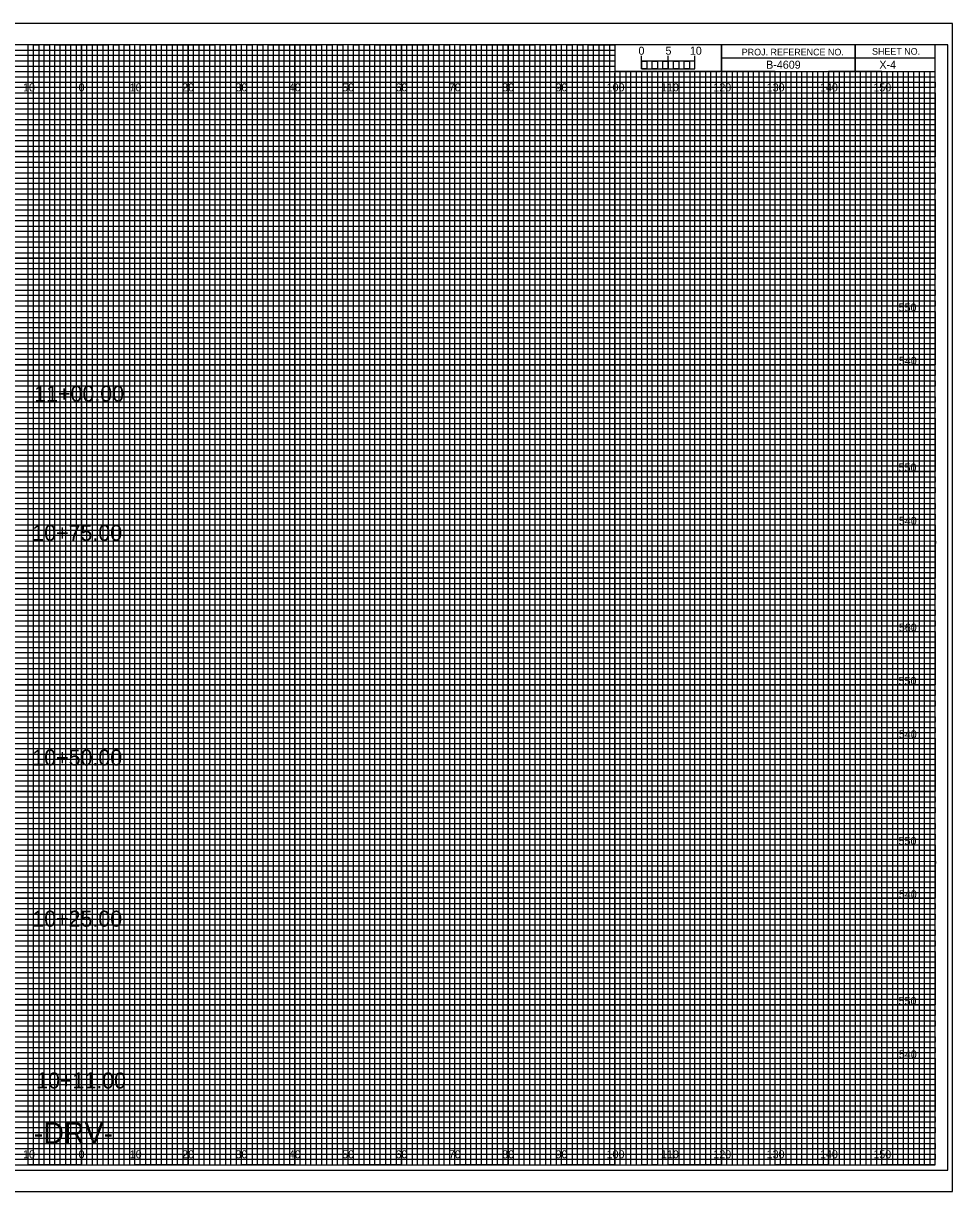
# Model space of a CAD drawing. Extents: x -13 to 323, y -5 to 214.
# Drawn here: x 149.1 to 323.3, y -5 to 214 of the extents above; entities that cross this region are included whole.
import ezdxf

# ---------------------------------------------------------------- set-up
doc = ezdxf.new("R2010")
doc.units = 0
for name, color, linetype in [('Prop XS Alignment Label', 7, 'Continuous'), ('Prop XS Bar Scale Labels', 7, 'Continuous'), ('Prop XS Elevation Labels', 7, 'Continuous'), ('Prop XS Offset Labels', 7, 'Continuous'), ('Prop XS Project Number', 7, 'Continuous'), ('Prop XS Sheet Number', 7, 'Continuous'), ('Prop XS Station Labels', 7, 'Continuous'), ('Sheet Cross Section CELL', 7, 'Continuous'), ('Sheet Cross Section Grid Major CELL', 7, 'Continuous'), ('Sheet Cross Section Grid Middle CELL', 7, 'Continuous'), ('Sheet Cross Section Grid Minor 1 CELL', 7, 'Continuous'), ('Sheet Cross Section Grid Minor 2 CELL', 7, 'Continuous'), ('Sheet Cross Section Scale CELL', 7, 'Continuous'), ('Sheet Cutting Line CELL', 7, 'Continuous'), ('Sheet DOT Grid CELL', 7, 'Continuous'), ('Sheet Plot Border Inside CELL', 7, 'Continuous'), ('Sheet Plot Border Outside CELL', 7, 'Continuous')]:
    doc.layers.add(name, color=color, linetype=linetype)

msp = doc.modelspace()

# ---------------------------------------------------------------- linework, layer by layer
at = {"layer": 'Sheet Cross Section CELL'}
for p, q in [((305, 210), (305, 205)), ((305, 205), (305, 210)), ((280, 207.5), (280, 205)), ((320, 207.49), (280, 207.49)), ((280, 205), (320, 205))]:
    msp.add_line(p, q, dxfattribs=at)
for points in [[(320, 210), (0, 210), (0, 0), (320, 0)], [(280, 210), (260, 210), (260, 205.03), (280, 205.03)], [(320, 210), (280, 210), (280, 205), (320, 205)]]:
    msp.add_lwpolyline(points, close=True, dxfattribs=at)
at = {"layer": 'Sheet Cross Section Grid Major CELL'}
for p, q in [((150, 210), (140, 210)), ((150, 0), (150, 210)), ((170, 210), (160, 210)), ((160, 210), (160, 0)), ((170, 0), (170, 210)), ((190, 210), (180, 210)), ((180, 210), (180, 0)), ((190, 0), (190, 210)), ((210, 210), (200, 210)), ((200, 210), (200, 0)), ((210, 0), (210, 210)), ((230, 210), (220, 210)), ((220, 210), (220, 0)), ((230, 0), (230, 210)), ((250, 210), (240, 210)), ((240, 210), (240, 0)), ((250, 0), (250, 210)), ((260, 210), (260, 0)), ((270, 0), (270, 205)), ((290, 205), (280, 205)), ((280, 205), (280, 0)), ((290, 0), (290, 205)), ((310, 205), (300, 205)), ((300, 205), (300, 0)), ((310, 0), (310, 205)), ((160, 0), (150, 0)), ((180, 0), (170, 0)), ((200, 0), (190, 0)), ((220, 0), (210, 0)), ((240, 0), (230, 0)), ((260, 0), (250, 0)), ((280, 0), (270, 0)), ((300, 0), (290, 0)), ((320, 0), (310, 0)), ((320, 0), (320, 0))]:
    msp.add_line(p, q, dxfattribs=at)
for points in [[(0, 200), (320, 200), (320, 190), (0, 190)], [(0, 180), (320, 180), (320, 170), (0, 170)], [(0, 160), (320, 160), (320, 150), (0, 150)], [(0, 140), (320, 140), (320, 130), (0, 130)], [(0, 120), (320, 120), (320, 110), (0, 110)], [(0, 100), (320, 100), (320, 90), (0, 90)], [(0, 80), (320, 80), (320, 70), (0, 70)], [(0, 60), (320, 60), (320, 50), (0, 50)], [(0, 40), (320, 40), (320, 30), (0, 30)], [(0, 20), (320, 20), (320, 10), (0, 10)]]:
    msp.add_lwpolyline(points, dxfattribs=at)
at = {"layer": 'Sheet Cross Section Grid Middle CELL'}
for points in [[(145, 0), (155, 0), (155, 210), (165, 210), (165, 0), (175, 0), (175, 210), (185, 210), (185, 0), (195, 0), (195, 210), (205, 210), (205, 0), (215, 0), (215, 210), (225, 210), (225, 0), (235, 0), (235, 210), (245, 210), (245, 0), (255, 0), (255, 210), (259.93, 210), (260, 210), (260, 205), (264.99, 205), (264.99, 0), (275, 0), (275, 205), (285, 205), (285, 0), (295, 0), (295, 205), (305, 205), (305, 0), (315, 0), (315, 205)], [(0, 205), (275, 205)], [(0, 185), (320, 185), (320, 195), (0, 195)], [(0, 165), (320, 165), (320, 175), (0, 175)], [(0, 145), (320, 145), (320, 155), (0, 155)], [(0, 125), (320, 125), (320, 135), (0, 135)], [(0, 105), (320, 105), (320, 115), (0, 115)], [(0, 85), (320, 85), (320, 95), (0, 95)], [(0, 65), (320, 65), (320, 75), (0, 75)], [(0, 45), (320, 45), (320, 55), (0, 55)], [(0, 25), (320, 25), (320, 35), (0, 35)], [(0, 5), (320, 5), (320, 15), (0, 15)]]:
    msp.add_lwpolyline(points, dxfattribs=at)
at = {"layer": 'Sheet Cross Section Grid Minor 1 CELL'}
for p, q in [((0, 209), (260, 209)), ((260, 209), (260, 207.98)), ((260, 207.98), (0, 207.98)), ((0, 207), (260, 207)), ((260, 205.89), (0, 205.89)), ((260, 207), (260, 205.89)), ((0, 204), (320, 204))]:
    msp.add_line(p, q, dxfattribs=at)
for points in [[(0, 203), (270, 203), (320, 203), (320, 202), (0, 202)], [(0, 201), (320, 201), (320, 199), (0, 199)], [(0, 198), (320, 198), (320, 197), (0, 196.98)], [(0, 196), (320, 196), (320, 194), (0, 194)], [(0, 193), (320, 193), (320, 192), (0, 192)], [(0, 191), (320, 191), (320, 189), (0, 189)], [(0, 188), (320, 188), (320, 187), (0, 187)], [(0, 186), (320, 186), (320, 184), (0, 184)], [(0, 183), (320, 183), (320, 182), (0, 182)], [(0, 181), (320, 181), (320, 179), (0, 179)], [(0, 178), (320, 178), (320, 177), (0, 177)], [(0, 176), (320, 176), (320, 173.95), (320, 173), (320, 172), (0, 172)], [(0, 174), (320, 174), (320, 173), (0, 173)], [(0, 171), (320, 171), (320, 169), (0, 169.03)], [(0, 169.03), (320, 169), (320, 168), (0, 168)], [(0, 167), (320, 167), (320, 166), (0, 166)], [(0, 164), (320, 164), (320, 163), (0, 163)], [(0, 162), (320, 162), (320, 161), (0, 161)], [(-0.07, 158.89), (320, 158.89), (320, 157.88), (-0.07, 157.88)], [(0, 157), (320, 157), (320, 156), (0, 156)], [(0, 154), (320, 154), (320, 153), (0, 153)], [(0, 152), (320, 152), (320, 151), (0, 151)], [(0, 149), (320, 149), (320, 148), (0, 148)], [(0, 147), (320, 147), (320, 146), (0, 146)], [(0, 144), (320, 144), (320, 143), (0, 143)], [(0, 142), (320, 142), (320, 141), (0, 141)], [(0, 139), (320, 139), (319.99, 137.98), (0, 138)], [(0, 137), (320, 137), (320, 136), (0, 136)], [(0, 134), (320, 134), (320, 133), (0, 133)], [(0, 132), (320, 132), (320, 131), (0, 131)], [(0, 129), (320, 129), (320, 128), (0, 128)], [(0, 127), (320, 127), (320, 126), (0, 126)], [(0, 124), (320, 124), (320, 123), (0, 123)], [(0, 122), (320, 122), (320, 121), (0, 121)], [(0, 119), (320, 119), (320, 118), (0, 118)], [(0, 116.99), (320.07, 116.91), (320, 116), (0, 116)], [(0, 114), (320, 114), (320, 113), (0, 113)], [(0, 112), (320, 112), (320, 111), (0, 111)], [(0, 109), (320, 109), (320, 108), (0, 108)], [(0, 107), (320, 107), (320, 106), (0, 106)], [(0, 104), (320, 104), (320, 103), (0, 103)], [(0, 102), (320, 102), (320, 101), (0, 101)], [(0, 99), (320, 99), (320, 98), (0, 98)], [(0, 97), (320, 97), (320, 96), (0, 96)], [(0, 94), (320, 94), (320, 93), (0, 93)], [(0, 92), (320, 92), (320, 91), (0, 91)], [(0, 89), (320, 89), (320, 88), (0, 88)], [(0, 87), (320, 87), (320, 86), (0, 86)], [(0, 84), (320, 84), (320, 83), (0, 83)], [(0, 82), (320, 82), (320, 81), (0, 81)], [(0, 79), (320, 79), (319.99, 77.98), (0, 78)], [(0, 77), (320, 77), (320, 76), (0, 76)], [(0, 74), (320, 74), (320, 73), (0, 73)], [(0, 72), (320, 72), (320, 71), (0, 71)], [(0, 69), (320, 69), (320, 68), (0, 68)], [(0, 67), (320, 67), (320, 66), (0, 66)], [(0, 64), (320, 64), (320, 63), (0, 63)], [(0, 62), (320, 62), (320, 61), (0, 61)], [(0, 59), (320, 59), (320, 58), (0, 58)], [(0, 56.99), (320.07, 56.91), (320, 56), (0, 56)], [(0, 54), (320, 54), (320, 53), (0, 53)], [(0, 52), (320, 52), (320, 51), (0, 51)], [(0, 49), (320, 49), (320, 48), (0, 48)], [(0, 47), (320, 47), (320, 46), (0, 46)], [(0, 44), (320, 44), (320, 43), (0, 43)], [(0, 42), (320, 42), (320, 41), (0, 41)], [(0, 39), (320, 39), (320, 38), (0, 38)], [(0, 37), (320, 37), (320, 36), (0, 36)], [(0, 34), (320, 34), (320, 33), (0, 33)], [(0, 32), (320, 32), (320, 31), (0, 31)], [(0, 29), (320, 29), (320, 28), (0, 28)], [(0, 27), (320, 27), (320, 26), (0, 26)], [(0, 24), (320, 24), (320, 23), (0, 23)], [(0, 22), (320, 22), (320, 21), (0, 21)], [(0, 19), (320, 19), (320, 18), (0, 18)], [(0, 17), (320, 17), (320, 16), (0, 16)], [(0, 14), (320, 14), (320, 13), (0, 13)], [(0, 12), (320, 12), (320, 11), (0, 11)], [(0, 9), (320, 9), (320, 8), (0, 8)], [(0, 7), (320, 7), (320, 6), (0, 6)], [(0, 4), (320, 4), (320, 3), (0, 3)], [(0, 2), (320, 2), (320, 1), (0, 1)]]:
    msp.add_lwpolyline(points, dxfattribs=at)
at = {"layer": 'Sheet Cross Section Grid Minor 2 CELL'}
for p, q in [((267, 205), (266.01, 205)), ((266.01, 205), (266.01, 0)), ((267, 0), (267, 205)), ((269, 205), (268, 205)), ((268, 205), (268, 0)), ((269, 0), (269, 205)), ((266.01, 0), (265, 0)), ((268, 0), (267, 0))]:
    msp.add_line(p, q, dxfattribs=at)
for points in [[(150, 0), (151, 0), (151, 210), (152, 210), (152, 0)], [(152, 0), (153, 0), (153, 210), (154, 210), (154, 0)], [(155, 0), (156, 0), (156, 210), (157, 210), (157, 0)], [(157, 0), (158, 0), (158, 210), (159, 210), (159, 0)], [(160, 0), (161, 0), (161, 210), (162, 210), (162, 0)], [(162, 0), (163, 0), (163, 210), (164, 210), (164, 0)], [(165, 0), (166, 0), (166, 210), (167, 210), (167, 0)], [(167, 0), (168, 0), (168, 210), (169, 210), (169, 0)], [(170, 0), (171, 0), (171, 210), (172, 210), (172, 0)], [(172, 0), (173, 0), (173, 210), (174, 210), (174, 0)], [(175, 0), (176, 0), (176, 210), (177, 210), (177, 0)], [(177, 0), (178, 0), (178, 210), (179, 210), (179, 0)], [(180, 0), (181, 0), (181, 210), (182, 210), (182, 0)], [(182, 0), (183, 0), (183, 210), (184, 210), (184, 0)], [(185, 0), (186, 0), (186, 210), (187, 210), (187, 0)], [(187, 0), (188, 0), (188, 210), (189, 210), (189, 0)], [(190, 0), (191, 0), (191, 210), (192, 210), (192, 0)], [(192, 0), (193, 0), (193, 210), (194, 210), (194, 0)], [(195, 0), (196, 0), (196, 210), (197, 210), (197, 0)], [(197, 0), (198, 0), (198, 210), (199, 210), (199, 0)], [(200, 0), (201, 0), (201, 210), (202, 210), (202, 0)], [(202, 0), (203, 0), (203, 210), (204, 210), (204, 0)], [(205, 0), (206, 0), (206, 210), (207, 210), (207, 0)], [(207, 0), (208, 0), (208, 210), (209, 210), (209, 0)], [(210, 0), (211, 0), (211, 210), (212, 210), (212, 0)], [(212, 0), (213, 0), (213, 210), (214, 210), (214, 0)], [(215, 0), (216, 0), (216, 210), (217, 210), (217, 0)], [(217, 0), (218, 0), (218, 210), (219, 210), (219, 0)], [(220, 0), (221, 0), (221, 210), (222, 210), (222, 0)], [(222, 0), (223, 0), (223, 210), (224, 210), (224, 0)], [(225, 0), (226, 0), (226, 210), (227, 210), (227, 0)], [(227, 0), (228, 0), (228, 210), (229, 210), (229, 0)], [(230, 0), (231, 0), (231, 210), (232, 210), (232, 0)], [(232, 0), (233, 0), (233, 210), (234, 210), (234, 0)], [(235, 0), (236, 0), (236, 210), (237, 210), (237, 0)], [(237, 0), (238, 0), (238, 210), (239, 210), (239, 0)], [(240, 0), (241, 0), (241, 210), (242, 210), (242, 0)], [(242, 0), (243, 0), (243, 210), (244, 210), (244, 0)], [(245, 0), (246, 0), (246, 210), (247, 210), (247, 0)], [(247, 0), (248, 0), (248, 210), (249, 210), (249, 0)], [(250, 0), (251, 0), (251, 210), (252, 210), (252, 0)], [(252, 0), (253, 0), (253, 210), (254, 210), (254, 0)], [(255, 0), (256, 0), (256, 210), (257, 210), (257, 0)], [(257, 0), (258, 0), (258, 210), (259, 210), (259, 0)], [(260, 0), (261, 0), (261, 205), (262.02, 205), (262.02, 0)], [(262, 0), (263, 0), (263, 205), (263.99, 205), (263.99, 0)], [(270, 0), (270.98, 0), (270.98, 205), (272, 205), (272, 0)], [(272, 0), (273, 0), (273, 205), (274.05, 205), (274.05, 0)], [(275, 0), (276, 0), (276, 205), (277, 205), (277, 0)], [(277, 0), (278, 0), (278, 205), (279, 205), (279, 0)], [(280, 0), (281, 0), (281, 205), (282, 205), (282, 0)], [(282, 0), (283, 0), (283, 205), (284, 205), (284, 0)], [(285, 0), (286, 0), (286, 205), (287, 205), (287, 0)], [(287, 0), (288, 0), (288, 205), (289, 205), (289, 0)], [(290, 0), (291, 0), (291, 205), (292, 205), (292, 0)], [(292, 0), (293, 0), (293, 205), (294, 205), (294, 0)], [(295, 0), (296, 0), (296, 205), (297, 205), (297, 0)], [(297, 0), (298, 0), (298, 205), (299, 205), (299, 0)], [(300, 0), (301, 0), (301, 205), (302, 205), (302, 0)], [(302, 0), (303, 0), (303, 205), (304, 205), (304, 0)], [(305, 0), (306, 0), (306, 205), (307, 205), (307, 0)], [(307, 0), (308, 0), (308, 205), (309, 205), (309, 0)], [(310, 0), (311, 0), (311, 205), (312, 205), (312, 0)], [(312, 0), (313, 0), (313, 205), (314, 205), (314, 0)], [(315, 0), (316, 0), (316, 205), (317, 205), (317, 0)], [(317, 0), (318, 0), (318, 205), (319, 205), (319, 0)]]:
    msp.add_lwpolyline(points, dxfattribs=at)
at = {"layer": 'Sheet Cross Section Scale CELL'}
for p, q in [((265, 205.49), (265, 207.9)), ((265, 206.9), (265, 207.9)), ((270, 205.49), (270, 207.9)), ((275, 205.49), (275, 207.9)), ((275, 206.9), (275, 207.9))]:
    msp.add_line(p, q, dxfattribs=at)
for points in [[(275, 206.9), (265, 206.9), (265, 205.49), (275, 205.49)], [(265, 206.9), (266, 206.9), (266, 205.49), (265, 205.49)], [(267, 206.9), (268, 206.9), (268, 205.49), (267, 205.49)], [(269, 206.9), (270, 206.9), (270, 205.49), (269, 205.49)], [(271, 206.9), (272, 206.9), (272, 205.49), (271, 205.49)], [(273, 206.9), (274, 206.9), (274, 205.49), (273, 205.49)]]:
    msp.add_lwpolyline(points, close=True, dxfattribs=at)
at = {"layer": 'Sheet Cutting Line CELL'}
for p, q in [((323.3, 214), (-13.4, 214)), ((-13.4, -5), (323.3, -5))]:
    msp.add_line(p, q, dxfattribs=at)
at = {"layer": 'Sheet DOT Grid CELL'}
for p, q in [((150, 0), (150, 210)), ((160, 0), (160, 210)), ((170, 0), (170, 210)), ((180, 0), (180, 210)), ((190, 0), (190, 210)), ((200, 0), (200, 210)), ((210, 0), (210, 210)), ((220, 0), (220, 210)), ((230, 0), (230, 210)), ((240, 0), (240, 210)), ((250, 0), (250, 210)), ((260, 0), (260, 204.69)), ((270, 0), (270, 204.69)), ((280, 0), (280, 204.69)), ((290, 0), (290, 204.69)), ((300, 0), (300, 204.69)), ((310, 0), (310, 204.69)), ((0, 200), (320, 200)), ((0, 190), (320, 190)), ((0, 180), (320, 180)), ((0, 170), (320, 170)), ((0, 160), (320, 160)), ((0, 150), (320, 150)), ((0, 140), (320, 140)), ((0, 130), (320, 130)), ((0, 120), (320, 120)), ((0, 110), (320, 110)), ((0, 100), (320, 100)), ((0, 90), (320, 90)), ((0, 80), (320, 80)), ((0, 70), (320, 70)), ((0, 60), (320, 60)), ((0, 50), (320, 50)), ((0, 40), (320, 40)), ((0, 30), (320, 30)), ((0, 20), (320, 20)), ((0, 10), (320, 10))]:
    msp.add_line(p, q, dxfattribs=at)
at = {"layer": 'Sheet Plot Border Inside CELL'}
msp.add_lwpolyline([(-10.8, -1), (322.4, -1), (322.4, 210), (-10.8, 210)], close=True, dxfattribs=at)
at = {"layer": 'Sheet Plot Border Outside CELL'}
msp.add_lwpolyline([(-13.4, -5), (323.3, -5), (323.3, 214), (-13.4, 214)], close=True, dxfattribs=at)

# ---------------------------------------------------------------- texts
at = {"layer": 'Prop XS Alignment Label'}
msp.add_text('-DRV-', height=4, dxfattribs=at).set_placement((151.06, 4))
at = {"layer": 'Prop XS Bar Scale Labels'}
for s, p in [('5', (269.47, 208.12)), ('10', (274.04, 208.12))]:
    msp.add_text(s, height=1.5, dxfattribs=at).set_placement(p)
at = {"layer": 'Prop XS Elevation Labels'}
for s, p in [('550', (313.17, 160)), ('540', (313.22, 150)), ('550', (313.17, 130)), ('540', (313.22, 120)), ('560', (313.22, 100)), ('550', (313.17, 90)), ('540', (313.22, 80)), ('550', (313.17, 60)), ('540', (313.22, 50)), ('550', (313.17, 30)), ('540', (313.22, 20))]:
    msp.add_text(s, height=1.5, dxfattribs=at).set_placement(p)
at = {"layer": 'Prop XS Offset Labels'}
for s, p in [('10', (149.04, 201.25)), ('0', (159.45, 201.25)), ('0', (159.45, 201.25)), ('10', (169.04, 201.25)), ('20', (178.86, 201.25)), ('30', (188.86, 201.25)), ('40', (198.86, 201.25)), ('50', (208.86, 201.25)), ('60', (218.86, 201.25)), ('70', (228.86, 201.25)), ('80', (238.86, 201.25)), ('90', (248.86, 201.25)), ('100', (258.44, 201.25)), ('110', (268.62, 201.25)), ('120', (278.44, 201.25)), ('130', (288.44, 201.25)), ('140', (298.44, 201.25)), ('150', (308.44, 201.25)), ('10', (149.04, 1.25)), ('0', (159.45, 1.25)), ('0', (159.45, 1.25)), ('10', (169.04, 1.25)), ('20', (178.86, 1.25)), ('30', (188.86, 1.25)), ('40', (198.86, 1.25)), ('50', (208.86, 1.25)), ('60', (218.86, 1.25)), ('70', (228.86, 1.25)), ('80', (238.86, 1.25)), ('90', (248.86, 1.25)), ('100', (258.44, 1.25)), ('110', (268.62, 1.25)), ('120', (278.44, 1.25)), ('130', (288.44, 1.25)), ('140', (298.44, 1.25)), ('150', (308.44, 1.25))]:
    msp.add_text(s, height=1.5, dxfattribs=at).set_placement(p)
at = {"layer": 'Prop XS Project Number'}
msp.add_text('B-4609', height=1.5, dxfattribs=at).set_placement((288.34, 205.5))
at = {"layer": 'Prop XS Sheet Number'}
msp.add_text('X-4', height=1.5, dxfattribs=at).set_placement((309.57, 205.5))
at = {"layer": 'Prop XS Station Labels'}
for s, p in [('11+00.00', (151.13, 143.09)), ('10+75.00', (150.77, 117)), ('10+50.00', (150.77, 74.88)), ('10+25.00', (150.77, 44.67)), ('10+11.00', (151.49, 14.34))]:
    msp.add_text(s, height=3, dxfattribs=at).set_placement(p)
at = {"layer": 'Sheet Cross Section CELL'}
for s, p in [('PROJ. REFERENCE NO.', (283.77, 207.99)), ('SHEET NO.', (308.19, 208.12))]:
    msp.add_text(s, height=1.25, dxfattribs=at).set_placement(p)
at = {"layer": 'Sheet Cross Section Scale CELL'}
msp.add_text('0', height=1.5, dxfattribs=at).set_placement((264.41, 208.12))

doc.saveas('drawing.dxf')
